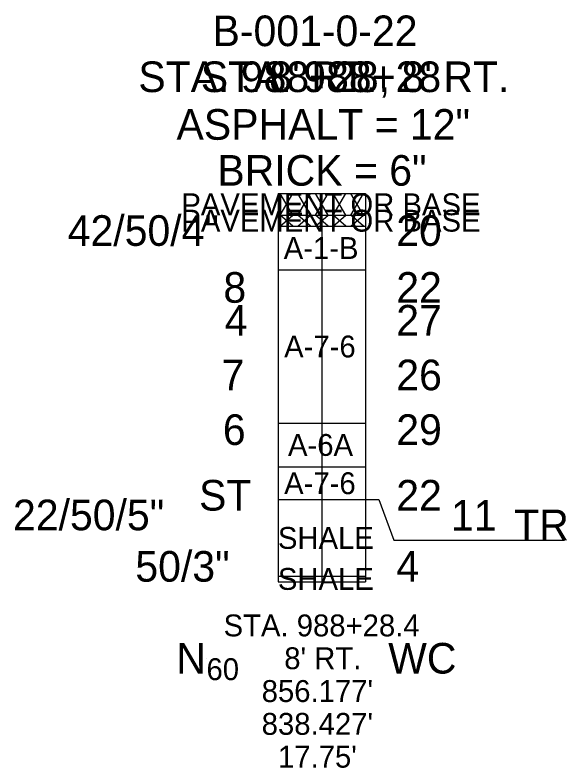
# Model space of a CAD drawing. Extents: x -1.4 to 1.12, y -2.63 to 0.81.
import ezdxf

# ---------------------------------------------------------------- set-up
doc = ezdxf.new("R2010")
doc.units = 0
for name, color, linetype in [('GT_Project_Soil_Boring', 7, 'Continuous'), ('GT_Project_Soil_Layers', 7, 'Continuous'), ('GT_Project_Text', 7, 'Continuous'), ('GT_Project_Text_2', 7, 'Continuous'), ('GT_Project_Text_3', 7, 'Continuous'), ('SC_Scratch1', 7, 'Continuous'), ('SC_Scratch2', 7, 'Continuous'), ('SC_Scratch3', 7, 'Continuous')]:
    doc.layers.add(name, color=color, linetype=linetype)

msp = doc.modelspace()

# ---------------------------------------------------------------- linework, layer by layer
at = {"layer": 'GT_Project_Soil_Boring'}
for p, q in [((-0.2, 0), (0.2, 0)), ((-0.2, 0), (-0.2, -1.775)), ((0, 0), (0, -1.775)), ((0.2, 0), (0.2, -1.775)), ((-0.2, -0.1), (0.2, -0.1)), ((-0.2, -0.15), (0.2, -0.15)), ((-0.2, -0.35), (0.2, -0.35)), ((-0.2, -1.05), (0.2, -1.05)), ((-0.2, -1.25), (0.2, -1.25)), ((-0.2, -1.4), (0.2, -1.4)), ((-0.2, -1.75), (0.2, -1.75)), ((-0.2, -1.775), (0.2, -1.775))]:
    msp.add_line(p, q, dxfattribs=at)
at = {"layer": 'GT_Project_Soil_Layers'}
for p, q in [((-0.1905, -0.1), (-0.1328, 0)), ((-0.1328, -0.1), (-0.1905, 0)), ((-0.1097, -0.1), (-0.052, 0)), ((-0.052, -0.1), (-0.1097, 0)), ((-0.0289, -0.1), (0.0289, 0)), ((0.0289, -0.1), (-0.0289, 0)), ((0.052, -0.1), (0.1097, 0)), ((0.1097, -0.1), (0.052, 0)), ((0.1328, -0.1), (0.1905, 0)), ((0.1905, -0.1), (0.1328, 0)), ((-0.2, -0.1), (-0.2, -0.1)), ((-0.1905, -0.15), (-0.1328, -0.1)), ((-0.1328, -0.15), (-0.1905, -0.1)), ((-0.1097, -0.15), (-0.052, -0.1)), ((-0.052, -0.15), (-0.1097, -0.1)), ((-0.0289, -0.15), (0.0289, -0.1)), ((0.0289, -0.15), (-0.0289, -0.1)), ((0.052, -0.15), (0.1097, -0.1)), ((0.1097, -0.15), (0.052, -0.1)), ((0.1328, -0.15), (0.1905, -0.1)), ((0.1905, -0.15), (0.1328, -0.1)), ((-0.2, -0.15), (-0.2, -0.15))]:
    msp.add_line(p, q, dxfattribs=at)
at = {"layer": 'GT_Project_Text'}
for p, q in [((0.3286, -1.5855), (1.1089, -1.5855)), ((-0.5272, -2.125), (-0.5272, -2.125))]:
    msp.add_line(p, q, dxfattribs=at)
msp.add_lwpolyline([(0.2, -1.4), (0.26, -1.4), (0.3286, -1.5855)], dxfattribs=at)

# ---------------------------------------------------------------- texts
for s, height, p in [('B-001-0-22', 0.14, (-0.4996, 0.6729)), ('ASPHALT = 12"', 0.14, (-0.6642, 0.245)), ('BRICK = 6"', 0.14, (-0.4776, 0.035)), ('42/50/4"', 0.14, (-1.1613, -0.24)), ('20', 0.14, (0.34, -0.24)), ('8', 0.14, (-0.45, -0.5)), ('22', 0.14, (0.34, -0.5)), ('4', 0.14, (-0.4437, -0.65)), ('27', 0.14, (0.34, -0.65)), ('7', 0.14, (-0.4582, -0.9)), ('26', 0.14, (0.34, -0.9)), ('6', 0.14, (-0.4524, -1.15)), ('29', 0.14, (0.34, -1.15)), ('ST', 0.14, (-0.5611, -1.45)), ('22', 0.14, (0.34, -1.45)), ('22/50/5"', 0.14, (-1.4113, -1.54)), ('11', 0.14, (0.59, -1.542)), ('TR', 0.14, (0.8789, -1.5855)), ('50/3"', 0.14, (-0.8523, -1.775)), ('4', 0.14, (0.34, -1.775)), ('N', 0.14, (-0.6652, -2.195)), ('WC', 0.14, (0.303, -2.195)), ('60', 0.1, (-0.5272, -2.225))]:
    msp.add_text(s, height=height, dxfattribs=at).set_placement(p)
at = {"layer": 'GT_Project_Text_2'}
msp.add_text("8' RT.", height=0.14, dxfattribs=at).set_placement((-0.2404, 0.4629))
at = {"layer": 'GT_Project_Text_3'}
msp.add_text('STA. 988+28', height=0.14, dxfattribs=at).set_placement((-0.5531, 0.4629))
at = {"layer": 'SC_Scratch1'}
for s, p in [('PAVEMENT OR BASE', (-0.6422, -0.1)), ('PAVEMENT OR BASE', (-0.6422, -0.175)), ('A-1-B', (-0.1744, -0.3)), ('A-7-6', (-0.1725, -0.75)), ('A-6A', (-0.1548, -1.2)), ('A-7-6', (-0.1725, -1.375)), ('SHALE', (-0.201, -1.625)), ('SHALE', (-0.201, -1.8125))]:
    msp.add_text(s, height=0.1, dxfattribs=at).set_placement(p)
at = {"layer": 'SC_Scratch2'}
for s, p in [('STA. 988+28.4', (-0.4492, -2.025)), ("8' RT.", (-0.1719, -2.175)), ("856.177'", (-0.275, -2.325)), ("838.427'", (-0.275, -2.475)), ("17.75'", (-0.2004, -2.625))]:
    msp.add_text(s, height=0.1, dxfattribs=at).set_placement(p)
at = {"layer": 'SC_Scratch3'}
msp.add_text("STA. 988+28, 8' RT.", height=0.14, dxfattribs=at).set_placement((-0.8386, 0.4629))

doc.saveas('drawing.dxf')
